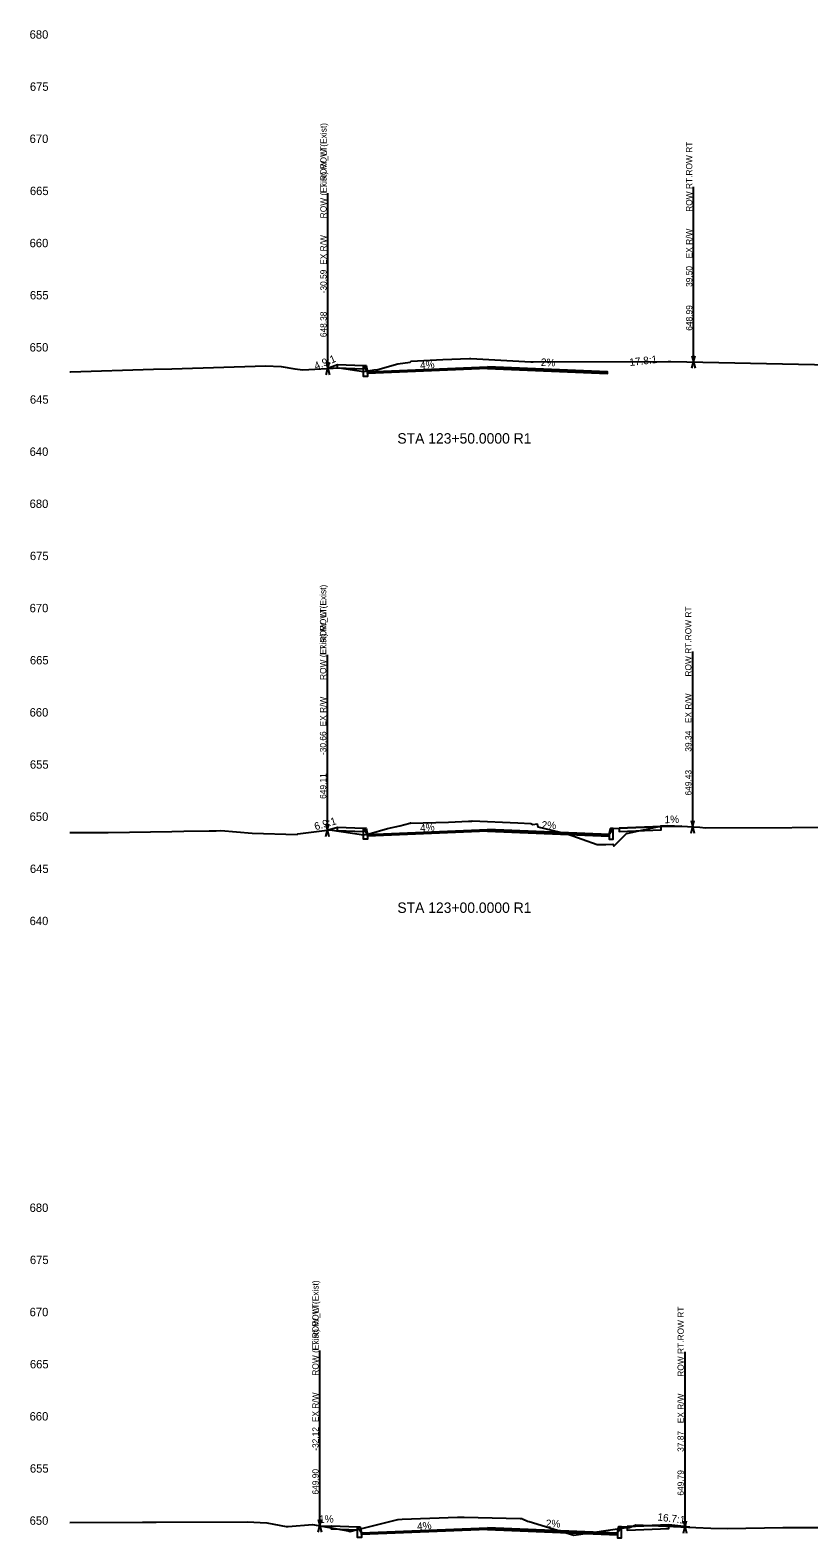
# Model space of a CAD drawing. Extents: x 2 to 741, y 16 to 2207.
# Drawn here: x 2.4 to 151.6, y 812.5 to 1101.6 of the extents above; entities that cross this region are included whole.
import ezdxf

# ---------------------------------------------------------------- set-up
doc = ezdxf.new("R2010")
doc.units = 0
for name, color, linetype in [('Draft_XS_Feature_Name', 7, 'Continuous'), ('Draft_XS_Label', 7, 'Continuous'), ('Draft_XS_Point_Label_Indicator', 7, 'Continuous'), ('Draft_XS_Terminator', 7, 'Continuous'), ('Draft_XS_Text', 7, 'Continuous'), ('E_ROW', 7, 'Continuous'), ('E_Terrain_Exterior', 7, 'Continuous'), ('E_Terrain_Points_Low', 7, 'Continuous'), ('Grade_Veg_Grass', 7, 'Continuous'), ('P_XS_Sections', 7, 'Continuous'), ('Road_Curb', 7, 'Continuous'), ('Road_Pave_Asphalt', 7, 'Continuous'), ('Road_Sidewalk', 7, 'Continuous'), ('Terrain_Design', 7, 'Continuous')]:
    doc.layers.add(name, color=color, linetype=linetype)

msp = doc.modelspace()

# ---------------------------------------------------------------- linework, layer by layer
at = {"layer": 'Draft_XS_Terminator'}
for p, q in [((59.41, 1036.75), (59.41, 1058.75)), ((59.41, 1036.75), (59.41, 1058.75)), ((129.5, 1037.99), (129.5, 1059.99)), ((59.34, 948.21), (59.34, 970.21)), ((59.34, 948.21), (59.34, 970.21)), ((129.34, 948.86), (129.34, 970.86)), ((57.88, 814.8), (57.88, 836.8)), ((57.88, 814.8), (57.88, 836.8)), ((127.87, 814.59), (127.87, 836.59))]:
    msp.add_line(p, q, dxfattribs=at)
at = {"layer": 'E_ROW'}
for p, q in [((59.41, 1036.75), (59.41, 1070.35)), ((59.41, 1036.75), (59.41, 1070.35)), ((129.5, 1037.99), (129.5, 1071.59)), ((129.2, 1036.79), (129.8, 1039.19)), ((129.2, 1039.19), (129.8, 1036.79)), ((59.11, 1035.55), (59.71, 1037.95)), ((59.11, 1037.95), (59.71, 1035.55)), ((59.11, 1035.55), (59.71, 1037.95)), ((59.11, 1037.95), (59.71, 1035.55)), ((59.34, 948.21), (59.34, 981.81)), ((59.34, 948.21), (59.34, 981.81)), ((129.34, 948.86), (129.34, 982.46)), ((59.04, 947.01), (59.64, 949.41)), ((59.04, 949.41), (59.64, 947.01)), ((59.04, 947.01), (59.64, 949.41)), ((59.04, 949.41), (59.64, 947.01)), ((129.04, 947.66), (129.64, 950.06)), ((129.04, 950.06), (129.64, 947.66)), ((57.88, 814.8), (57.88, 848.4)), ((57.88, 814.8), (57.88, 848.4)), ((127.87, 814.59), (127.87, 848.19)), ((57.58, 813.6), (58.18, 816)), ((57.58, 816), (58.18, 813.6)), ((57.58, 813.6), (58.18, 816)), ((57.58, 816), (58.18, 813.6)), ((127.57, 813.39), (128.17, 815.79)), ((127.57, 815.79), (128.17, 813.39))]:
    msp.add_line(p, q, dxfattribs=at)
at = {"layer": 'E_Terrain_Exterior'}
for points in [[(10, 1036.11), (10.12, 1036.11), (26.02, 1036.62), (29.53, 1036.71), (47.5, 1037.28), (50.46, 1037.1), (53.08, 1036.71), (54.64, 1036.48), (54.65, 1036.48), (61.56, 1036.87), (66.25, 1036.19), (68.27, 1036.5), (69.03, 1036.53), (72.8, 1037.64), (75.17, 1037.99), (75.23, 1038), (75.37, 1038.13), (81.44, 1038.5), (86.54, 1038.66), (86.69, 1038.68), (86.84, 1038.67), (98.33, 1038.03), (98.52, 1038.03), (98.62, 1038.03), (98.76, 1038.03), (124.67, 1038.08), (124.74, 1038.08), (124.91, 1038.08), (125.17, 1038.08), (177.12, 1037)], [(10, 947.79), (15.86, 947.76), (17.33, 947.78), (29.49, 947.97), (31.83, 948), (36.68, 948.07), (37.99, 948.11), (38.92, 948.14), (44.89, 947.61), (53.56, 947.36), (53.69, 947.5), (59.79, 948.27), (64.14, 947.63), (66.24, 947.31), (67.35, 947.51), (70.86, 948.55), (73.21, 949.01), (75.12, 949.53), (75.26, 949.59), (75.29, 949.53), (82.56, 949.75), (86.39, 949.94), (86.52, 949.93), (86.96, 949.96), (87.09, 949.97), (95.82, 949.61), (98.31, 949.48), (98.59, 949.37), (98.68, 949.31), (99.52, 949.42), (99.66, 948.88), (105.27, 947.51), (111.04, 945.47), (112.67, 945.43), (114.03, 945.52), (114.21, 945.13), (116.64, 947.54), (123.2, 948.98), (123.26, 949.07), (124.57, 949.08), (127.21, 949), (130.72, 948.76), (131.8, 948.66), (164.96, 948.76)], [(10, 815.42), (23.87, 815.5), (26.51, 815.51), (43.93, 815.59), (47.7, 815.39), (49.07, 815.12), (51.46, 814.66), (51.57, 814.67), (51.8, 814.69), (56.51, 815.04), (63.33, 813.85), (63.72, 813.7), (64.16, 813.86), (72.85, 815.99), (72.88, 816), (73.65, 816.05), (84.28, 816.44), (84.7, 816.46), (84.73, 816.45), (85.53, 816.47), (96.26, 816.2), (96.65, 816.18), (96.7, 816.17), (97.68, 815.71), (97.97, 815.61), (106.59, 812.99), (116.68, 814.45), (117.08, 814.49), (117.21, 814.49), (118.46, 815.02), (132.8, 814.36), (136.04, 814.31), (146.64, 814.48), (147.76, 814.47), (159.6, 814.45)]]:
    msp.add_lwpolyline(points, dxfattribs=at)
at = {"layer": 'Grade_Veg_Grass'}
for points in [[(59.25, 1036.74), (59.25, 1036.74), (61.25, 1037.5)], [(59.26, 948.2), (59.26, 948.2), (61.26, 948.77)], [(114.08, 948.55), (115.27, 948.6)], [(127.28, 949), (123.28, 948.92), (123.28, 948.92)], [(58.09, 814.76), (60.09, 814.82), (60.09, 814.82)], [(115.67, 814.59), (116.79, 814.64)], [(128.79, 814.54), (124.79, 814.96), (124.79, 814.96)]]:
    msp.add_lwpolyline(points, dxfattribs=at)
at = {"layer": 'Road_Curb'}
for points in [[(67, 1036.13), (67, 1035.22), (66.25, 1035.22), (66.25, 1037.3), (66.77, 1037.3), (67, 1036.13)], [(67.01, 947.4), (67.01, 946.48), (66.26, 946.48), (66.26, 948.57), (66.78, 948.57), (67.01, 947.4)], [(113.33, 947.39), (113.33, 946.47), (114.08, 946.47), (114.08, 948.55), (113.56, 948.55), (113.33, 947.39)], [(65.84, 813.45), (65.84, 812.54), (65.09, 812.54), (65.09, 814.62), (65.61, 814.62), (65.84, 813.45)], [(114.92, 813.42), (114.92, 812.51), (115.67, 812.51), (115.67, 814.59), (115.15, 814.59), (114.92, 813.42)]]:
    msp.add_lwpolyline(points, dxfattribs=at)
at = {"layer": 'Road_Pave_Asphalt'}
for points in [[(90, 1037.05), (90, 1036.72), (67, 1035.8), (67, 1036.13), (90, 1037.05)], [(90, 1037.05), (90, 1036.72), (113, 1035.8), (113, 1036.13), (90, 1037.05)], [(90, 948.32), (90, 947.99), (67.01, 947.07), (67.01, 947.4), (90, 948.32)], [(90, 948.32), (90, 947.99), (113.33, 947.05), (113.33, 947.39), (90, 948.32)], [(90, 814.42), (90, 814.09), (65.84, 813.12), (65.84, 813.45), (90, 814.42)], [(90, 814.42), (90, 814.09), (114.92, 813.09), (114.92, 813.42), (90, 814.42)]]:
    msp.add_lwpolyline(points, dxfattribs=at)
at = {"layer": 'Road_Sidewalk'}
for points in [[(66.25, 1037.3), (66.25, 1036.63), (61.25, 1036.83), (61.25, 1037.5), (66.25, 1037.3)], [(66.26, 948.57), (66.26, 947.9), (61.26, 948.1), (61.26, 948.77), (66.26, 948.57)], [(115.27, 948.6), (115.27, 947.94), (123.28, 948.26), (123.28, 948.92), (115.27, 948.6)], [(65.09, 814.62), (65.09, 813.95), (60.09, 814.15), (60.09, 814.82), (65.09, 814.62)], [(116.79, 814.64), (116.79, 813.97), (124.79, 814.29), (124.79, 814.96), (116.79, 814.64)]]:
    msp.add_lwpolyline(points, dxfattribs=at)
at = {"layer": 'Terrain_Design'}
for points in [[(59.25, 1036.74), (61.25, 1037.5), (66.25, 1037.3), (66.77, 1037.3), (67, 1036.13), (90, 1037.05), (113, 1036.13)], [(59.25, 1036.74), (61.25, 1037.5), (66.25, 1037.3), (66.77, 1036.49), (67, 1036.13), (90, 1037.05), (113, 1036.13)], [(59.26, 948.2), (59.26, 948.2), (61.26, 948.77), (66.26, 948.57), (66.78, 948.57), (67.01, 947.4), (90, 948.32), (113.33, 947.39), (113.56, 948.55), (114.08, 948.55), (115.27, 948.6), (123.28, 948.92), (127.28, 949)], [(59.26, 948.2), (59.26, 948.2), (61.26, 948.77), (66.26, 948.57), (66.78, 947.76), (67.01, 947.4), (90, 948.32), (113.33, 947.39), (113.56, 947.74), (114.08, 948.55), (115.27, 948.6), (123.28, 948.92), (127.28, 949)], [(58.09, 814.76), (60.09, 814.82), (65.09, 814.62), (65.61, 814.62), (65.84, 813.45), (90, 814.42), (114.92, 813.42), (115.15, 814.59), (115.67, 814.59), (116.79, 814.64), (124.79, 814.96), (128.79, 814.54)], [(58.09, 814.76), (60.09, 814.82), (65.09, 814.62), (65.61, 813.81), (65.84, 813.45), (90, 814.42), (114.92, 813.42), (115.15, 813.78), (115.67, 814.59), (116.79, 814.64), (124.79, 814.96), (128.79, 814.54)]]:
    msp.add_lwpolyline(points, dxfattribs=at)

# ---------------------------------------------------------------- texts
at = {"layer": 'Draft_XS_Feature_Name'}
for s, p in [('ROW (Exist).ROW (Exist)', (59.17, 1065.55)), ('ROW_LT.ROW_LT', (59.17, 1065.55)), ('ROW RT.ROW RT', (129.26, 1066.79)), ('ROW (Exist).ROW (Exist)', (59.1, 977.01)), ('ROW_LT.ROW_LT', (59.1, 977.01)), ('ROW RT.ROW RT', (129.1, 977.66)), ('ROW (Exist).ROW (Exist)', (57.64, 843.6)), ('ROW_LT.ROW_LT', (57.64, 843.6)), ('ROW RT.ROW RT', (127.63, 843.39))]:
    msp.add_text(s, height=1.2, rotation=90, dxfattribs=at).set_placement(p)
at = {"layer": 'Draft_XS_Label'}
for s, p in [('-30.59', (59.17, 1051.15)), ('-30.59', (59.17, 1051.15)), ('39.50', (129.26, 1052.39)), ('648.38', (59.17, 1042.75)), ('648.38', (59.17, 1042.75)), ('648.99', (129.26, 1043.99)), ('-30.66', (59.1, 962.61)), ('-30.66', (59.1, 962.61)), ('39.34', (129.1, 963.26)), ('649.11', (59.1, 954.21)), ('649.11', (59.1, 954.21)), ('649.43', (129.1, 954.86)), ('-32.12', (57.64, 829.2)), ('-32.12', (57.64, 829.2)), ('37.87', (127.63, 828.99)), ('649.90', (57.64, 820.8)), ('649.90', (57.64, 820.8)), ('649.79', (127.63, 820.59))]:
    msp.add_text(s, height=1.2, rotation=90, dxfattribs=at).set_placement(p)
at = {"layer": 'Draft_XS_Point_Label_Indicator'}
for p in [(59.24, 1036.73), (61.24, 1037.49), (66.24, 1037.29), (66.76, 1037.29), (66.99, 1036.12), (66.99, 1035.2), (112.99, 1036.12), (61.25, 948.76), (66.25, 948.56), (66.77, 948.56), (113.54, 948.54), (114.07, 948.54), (115.26, 948.59), (123.27, 948.91), (127.27, 948.99), (59.25, 948.19), (67, 947.39), (67, 946.47), (113.32, 947.38), (113.32, 946.46), (58.08, 814.75), (60.08, 814.81), (65.08, 814.61), (65.6, 814.61), (65.83, 813.44), (65.83, 812.53), (114.91, 813.41), (114.91, 812.5), (115.14, 814.58), (115.66, 814.58), (116.78, 814.62), (124.78, 814.94), (128.78, 814.53)]:
    msp.add_text('X', height=0.024, dxfattribs=at).set_placement(p)
at = {"layer": 'Draft_XS_Text'}
for s, height, p in [('680', 1.608, (2.26, 1100)), ('675', 1.608, (2.32, 1090)), ('670', 1.608, (2.26, 1080)), ('665', 1.608, (2.32, 1070)), ('660', 1.608, (2.26, 1060)), ('655', 1.608, (2.32, 1050)), ('650', 1.608, (2.26, 1040)), ('645', 1.608, (2.32, 1030)), ('STA 123+50.0000 R1', 1.992, (72.74, 1022.35)), ('640', 1.608, (2.26, 1020)), ('680', 1.608, (2.26, 1010)), ('675', 1.608, (2.32, 1000)), ('670', 1.608, (2.26, 990)), ('665', 1.608, (2.32, 980)), ('660', 1.608, (2.26, 970)), ('655', 1.608, (2.32, 960)), ('650', 1.608, (2.26, 950)), ('645', 1.608, (2.32, 940)), ('STA 123+00.0000 R1', 1.992, (72.74, 932.35)), ('640', 1.608, (2.26, 930)), ('680', 1.608, (2.26, 875)), ('675', 1.608, (2.32, 865)), ('670', 1.608, (2.26, 855)), ('665', 1.608, (2.32, 845)), ('660', 1.608, (2.26, 835)), ('655', 1.608, (2.32, 825)), ('650', 1.608, (2.26, 815))]:
    msp.add_text(s, height=height, dxfattribs=at).set_placement(p)
for s, rotation, p in [('4.9:1', 22.071, (57.14, 1036.48)), ('4%', 4.5657, (77.14, 1036.63)), ('2%', 357.7094, (100.21, 1037.25)), ('17.8:1', 6.4129, (117.29, 1037.22)), ('6.9:1', 16.0968, (57.06, 948.18)), ('4%', 4.5668, (77.15, 947.9)), ('2%', 357.7094, (100.37, 948.51)), ('1%', 1.0673, (123.96, 949.54)), ('1%', 1.6469, (57.76, 815.35)), ('4%', 4.4566, (76.56, 813.98)), ('2%', 357.7094, (101.17, 814.57)), ('16.7:1', 353.1746, (122.52, 815.83))]:
    msp.add_text(s, height=1.44, rotation=rotation, dxfattribs=at).set_placement(p)
at = {"layer": 'E_ROW'}
for p in [(59.17, 1056.63), (59.17, 1056.63), (129.26, 1057.87), (129.1, 968.74), (59.1, 968.1), (59.1, 968.1), (57.64, 834.68), (57.64, 834.68), (127.63, 834.47)]:
    msp.add_text('EX R/W', height=1.2, rotation=90, dxfattribs=at).set_placement(p)
at = {"layer": 'E_Terrain_Points_Low'}
for p in [(89.99, 1037.04), (89.99, 948.31), (89.99, 814.41)]:
    msp.add_text('X', height=0.024, dxfattribs=at).set_placement(p)
at = {"layer": 'P_XS_Sections'}
for p in [(10, 1020), (10, 930)]:
    msp.add_text('-', height=0.0001, dxfattribs=at).set_placement(p)

doc.saveas('drawing.dxf')
